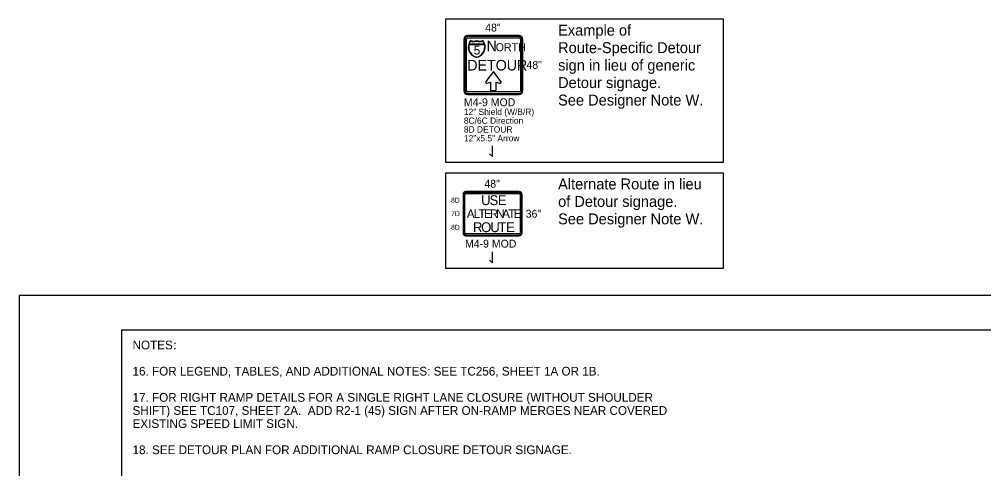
# Model space of a CAD drawing. Extents: x 99999 to 100116, y 99995 to 100013.
# Drawn here: x 100039.06 to 100047.9, y 100009.1 to 100013.22 of the extents above; entities that cross this region are included whole.
import ezdxf

# ---------------------------------------------------------------- set-up
doc = ezdxf.new("R2010")
doc.units = 0
for name, color, linetype in [('SH_GI_GeneralNotesBodyText', 7, 'Continuous'), ('SH_GI_PlotLimits', 7, 'Continuous'), ('SH_GI_SheetBorder', 7, 'Continuous'), ('TR_SN_ConstructionSigns', 7, 'Continuous'), ('TR_WZ_WorkZoneDetails', 7, 'Continuous')]:
    doc.layers.add(name, color=color, linetype=linetype)

msp = doc.modelspace()

# ---------------------------------------------------------------- linework, layer by layer
at = {"layer": 'SH_GI_PlotLimits'}
msp.add_lwpolyline([(100039.0625, 99999.6875), (100056.0625, 99999.6875), (100056.0625, 100010.6875), (100039.0625, 100010.6875)], close=True, dxfattribs=at)
at = {"layer": 'SH_GI_SheetBorder'}
for q in [(100040, 100000), (100055.75, 100010.375)]:
    msp.add_line((100040, 100010.375), q, dxfattribs=at)
at = {"layer": 'TR_SN_ConstructionSigns'}
for p, q in [((100043.1354, 100013.0373), (100043.1354, 100012.5648)), ((100043.1438, 100013.0373), (100043.1438, 100012.5648)), ((100043.1579, 100012.5648), (100043.1579, 100013.0373)), ((100043.6416, 100013.0711), (100043.1691, 100013.0711)), ((100043.6416, 100013.0626), (100043.1691, 100013.0626)), ((100043.1691, 100013.0486), (100043.6416, 100013.0486)), ((100043.6529, 100013.0373), (100043.6529, 100012.5648)), ((100043.6669, 100012.5648), (100043.6669, 100013.0373)), ((100043.6754, 100012.5648), (100043.6754, 100013.0373)), ((100043.3228, 100012.9875), (100043.1823, 100012.9875)), ((100043.1823, 100012.9875), (100043.3228, 100012.9875)), ((100043.1834, 100012.9912), (100043.3217, 100012.9912)), ((100043.3217, 100012.9912), (100043.1834, 100012.9912)), ((100043.6416, 100012.5536), (100043.1691, 100012.5536)), ((100043.1691, 100012.5395), (100043.6416, 100012.5395)), ((100043.1691, 100012.5311), (100043.6416, 100012.5311)), ((100043.6424, 100011.6405), (100043.153, 100011.6405)), ((100043.6424, 100011.6335), (100043.153, 100011.6335)), ((100043.153, 100011.6236), (100043.6424, 100011.6236)), ((100043.1277, 100011.6152), (100043.1277, 100011.2608)), ((100043.1347, 100011.6152), (100043.1347, 100011.2608)), ((100043.1446, 100011.2608), (100043.1446, 100011.6152)), ((100043.6508, 100011.6152), (100043.6508, 100011.2608)), ((100043.6607, 100011.2608), (100043.6607, 100011.6152)), ((100043.6677, 100011.2608), (100043.6677, 100011.6152)), ((100043.6424, 100011.2524), (100043.153, 100011.2524)), ((100043.153, 100011.2425), (100043.6424, 100011.2425)), ((100043.153, 100011.2355), (100043.6424, 100011.2355))]:
    msp.add_line(p, q, dxfattribs=at)
msp.add_lwpolyline([(100043.3367, 100012.6494), (100043.3356, 100012.6478), (100043.335, 100012.6461), (100043.3347, 100012.6441), (100043.3348, 100012.6424), (100043.335, 100012.6412), (100043.3356, 100012.6398), (100043.3373, 100012.6375), (100043.3386, 100012.6364), (100043.34, 100012.6355), (100043.3417, 100012.6348), (100043.3432, 100012.6345), (100043.3447, 100012.6343), (100043.3465, 100012.6343), (100043.3478, 100012.6346), (100043.3795, 100012.6424), (100043.3795, 100012.5671), (100043.4307, 100012.5671), (100043.4307, 100012.6429), (100043.4617, 100012.6337), (100043.4647, 100012.6331), (100043.4681, 100012.6334), (100043.4703, 100012.6342), (100043.4733, 100012.6362), (100043.4752, 100012.6389), (100043.476, 100012.6414), (100043.4761, 100012.6436), (100043.4754, 100012.6463), (100043.4746, 100012.6477), (100043.4051, 100012.7405), (100043.3367, 100012.6494)], dxfattribs=at)
for centre, radius, start, end in [((100043.1691, 100013.0373), 0.0337, 90, 180), ((100043.1691, 100013.0373), 0.0253, 90, 180), ((100043.1691, 100013.0373), 0.0113, 90, 180), ((100043.6416, 100013.0373), 0.0338, 360, 90), ((100043.6416, 100013.0373), 0.0253, 360, 90), ((100043.6416, 100013.0373), 0.0113, 360, 90), ((100043.2725, 100012.9642), 0.0973, 142.16169, 258.18105), ((100043.2715, 100012.9633), 0.0925, 164.85517, 258.18105), ((100043.2715, 100012.9633), 0.0925, 164.85517, 258.18105), ((100043.2715, 100012.9633), 0.0925, 142.16169, 162.48397), ((100043.2715, 100012.9633), 0.0925, 142.16169, 162.48397), ((100043.2245, 100013.1212), 0.1014, 253.48525, 286.04538), ((100043.2259, 100013.1124), 0.0964, 253.48525, 286.04538), ((100043.2259, 100013.1124), 0.0964, 253.48525, 286.04538), ((100043.2806, 100013.1212), 0.1014, 253.95462, 286.51475), ((100043.2792, 100013.1124), 0.0964, 253.95462, 286.51475), ((100043.2792, 100013.1124), 0.0964, 253.95462, 286.51475), ((100043.2325, 100012.9642), 0.0974, 281.90384, 37.84925), ((100043.2335, 100012.9633), 0.0925, 281.90384, 15.1558), ((100043.2335, 100012.9633), 0.0925, 281.90384, 15.1558), ((100043.2335, 100012.9633), 0.0925, 17.52691, 37.84925), ((100043.2335, 100012.9633), 0.0925, 17.52691, 37.84925), ((100043.1691, 100012.5648), 0.0338, 180, 270), ((100043.1691, 100012.5648), 0.0253, 180, 270), ((100043.1691, 100012.5648), 0.0113, 180, 270), ((100043.6416, 100012.5648), 0.0337, 270, 360), ((100043.6416, 100012.5648), 0.0253, 270, 0), ((100043.6416, 100012.5648), 0.0113, 270, 0), ((100043.153, 100011.6152), 0.0253, 90, 180), ((100043.153, 100011.6152), 0.0183, 90, 180), ((100043.153, 100011.6152), 0.00844, 90, 180), ((100043.6424, 100011.6152), 0.0253, 360, 90), ((100043.6424, 100011.6152), 0.0183, 360, 90), ((100043.6424, 100011.6152), 0.00844, 360, 90), ((100043.153, 100011.2608), 0.0253, 180, 270), ((100043.153, 100011.2608), 0.0183, 180, 270), ((100043.153, 100011.2608), 0.00844, 180, 270), ((100043.6424, 100011.2608), 0.0253, 270, 360), ((100043.6424, 100011.2608), 0.0183, 270, 0), ((100043.6424, 100011.2608), 0.00844, 270, 0)]:
    msp.add_arc(centre, radius, start, end, dxfattribs=at)
at = {"layer": 'TR_WZ_WorkZoneDetails'}
for p, q in [((100043.3963, 100011.9605), (100043.3963, 100012.0605)), ((100043.3713, 100011.9855), (100043.3963, 100011.9605)), ((100043.3963, 100010.9875), (100043.3963, 100011.0875)), ((100043.3713, 100011.0125), (100043.3963, 100010.9875))]:
    msp.add_line(p, q, dxfattribs=at)
for points in [[(100042.9666, 100011.9105), (100045.5143, 100011.9105), (100045.5143, 100013.2191), (100042.9666, 100013.2191)], [(100042.9666, 100010.9375), (100045.5143, 100010.9375), (100045.5143, 100011.8105), (100042.9666, 100011.8105)]]:
    msp.add_lwpolyline(points, close=True, dxfattribs=at)

# ---------------------------------------------------------------- texts
at = {"layer": 'SH_GI_GeneralNotesBodyText'}
for s, p in [('NOTES', (100040.1, 100010.195)), (':', (100040.4743, 100010.195)), ('16. FOR LEGEND, TABLES, AND ADDITIONAL NOTES: SEE TC256, SHEET 1A OR 1B.', (100040.1, 100009.955)), ('17. FOR RIGHT RAMP DETAILS FOR A SINGLE RIGHT LANE CLOSURE (WITHOUT SHOULDER ', (100040.1, 100009.715)), ('SHIFT) SEE TC107, SHEET 2A.  ADD R2-1 (45) SIGN AFTER ON-RAMP MERGES NEAR COVERED ', (100040.1, 100009.595)), ('EXISTING SPEED LIMIT SIGN.', (100040.1, 100009.475)), ('18. SEE DETOUR PLAN FOR ADDITIONAL RAMP CLOSURE DETOUR SIGNAGE.', (100040.1, 100009.235))]:
    msp.add_text(s, height=0.08, rotation=360, dxfattribs=at).set_placement(p)
at = {"layer": 'TR_SN_ConstructionSigns'}
for s, height, p in [('48"', 0.072, (100043.3306, 100013.1071)), ('5', 0.081, (100043.2253, 100012.8951)), ('N', 0.0972, (100043.3432, 100012.9267)), ('ORTH', 0.0729, (100043.4264, 100012.9267)), ('DETOUR', 0.0972, (100043.1668, 100012.7497)), ('48"', 0.072, (100043.7086, 100012.7651)), ('M4-9 MOD', 0.072, (100043.1354, 100012.4231)), ('12" Shield (W/B/R)', 0.0576, (100043.1354, 100012.3424)), ('8C/6C Direction', 0.0576, (100043.1354, 100012.2618)), ('8D DETOUR', 0.0576, (100043.1354, 100012.1811)), ('12"x5.5" Arrow', 0.0576, (100043.1354, 100012.1005)), ('48"', 0.072, (100043.323, 100011.6765)), ('36"', 0.072, (100043.7015, 100011.402)), ('M4-9 MOD', 0.072, (100043.1457, 100011.1275))]:
    msp.add_text(s, height=height, rotation=360, dxfattribs=at).set_placement(p)
for s, height, p in [('8D', 0.045, (100043.018, 100011.5392)), ('U', 0.09, (100043.2933, 100011.5167)), ('S', 0.09, (100043.3698, 100011.5167)), ('E', 0.09, (100043.4463, 100011.5167)), ('7D', 0.045, (100043.018, 100011.4155)), ('A', 0.0787, (100043.1626, 100011.3986)), ('L', 0.0787, (100043.2241, 100011.3986)), ('T', 0.0787, (100043.269, 100011.3986)), ('E', 0.0787, (100043.3201, 100011.3986)), ('R', 0.0787, (100043.3737, 100011.3986)), ('N', 0.0787, (100043.4312, 100011.3986)), ('A', 0.0787, (100043.4863, 100011.3986)), ('T', 0.0787, (100043.5414, 100011.3986)), ('E', 0.0787, (100043.5926, 100011.3986)), ('R', 0.09, (100043.2186, 100011.2692)), ('O', 0.09, (100043.2933, 100011.2692)), ('U', 0.09, (100043.377, 100011.2692)), ('T', 0.09, (100043.4517, 100011.2692)), ('E', 0.09, (100043.521, 100011.2692)), ('8D', 0.045, (100043.018, 100011.2917))]:
    msp.add_text(s, height=height, dxfattribs=at).set_placement(p)
at = {"layer": 'TR_WZ_WorkZoneDetails'}
for s, p in [('Example of ', (100043.9983, 100013.0691)), ('Route-Specific Detour ', (100043.9983, 100012.9091)), ('sign in lieu of generic ', (100043.9983, 100012.7491)), ('Detour signage.', (100043.9983, 100012.5891)), ('See Designer Note W.', (100043.9983, 100012.4291)), ('Alternate Route in lieu ', (100043.9983, 100011.6605)), ('of Detour signage.', (100043.9983, 100011.5005)), ('See Designer Note W.', (100043.9983, 100011.3405))]:
    msp.add_text(s, height=0.1, dxfattribs=at).set_placement(p)

doc.saveas('drawing.dxf')
